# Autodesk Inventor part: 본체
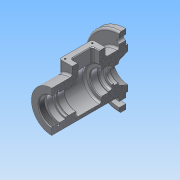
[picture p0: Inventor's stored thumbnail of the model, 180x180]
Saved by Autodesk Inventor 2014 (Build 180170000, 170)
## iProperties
Created: 2017-05
Part Number: 본체
Material: 알루미늄 6061
Document SubType Name: Modeling
Designer: SCD-A14
Density: 2.71 g/cm^3
Appearance: 알루미늄 - 평지
Mass: 682.14 g
Surface Area: 618.19 cm^2
Volume: 251.712 cm^3
Author: SCD-A14
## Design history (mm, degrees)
sketch "스케치1"
  geometry: C1 r 31 at (0, 0); 1 further point
  constraints: 1 centre point, 1 coincident
  dimensions: "d0" = 62 diameter of C1
extrude "돌출1" new body sketch "스케치1" distance "d1" = 115; taper "d2" = 0 deg
sketch "스케치2"
  geometry: 2 further points
  constraints: 1 coincident
hole "구멍1" sketch "스케치2" at (0, 0) diameter "d3" = 40.376; stored, may be unused: countersink angle "d7" = 90 deg, drill point angle "d9" = 0 deg; dims "d4" = 6, "d5" = 4, "d6" = 2, "d8" = 9
sketch "스케치3"
  geometry: C1 r 24 at (0, 0); 1 further point
  constraints: 1 centre point, 1 coincident
  dimensions: "d10" = 48 diameter of C1
extrude "돌출2" cut sketch "스케치3" distance "d11" = 3; taper "d12" = 0 deg
sketch "스케치4"
  geometry: C1 r 20 at (0, 0); 1 further point
  constraints: 1 centre point, 1 coincident
  dimensions: "d13" = 40 diameter of C1
extrude "돌출3" cut sketch "스케치4" distance "d14" = 9; taper "d15" = 0 deg
node "작업 평면1"
sketch "스케치5"
  geometry: C1 r 18.5 at (0, 0); 1 further point
  constraints: 1 centre point, 1 coincident
  dimensions: "d17" = 37 diameter of C1
extrude "돌출4" cut sketch "스케치5" distance "d18" = 1.75; taper "d19" = 0 deg
sketch "스케치6"
  geometry: C1 r 17.5 at (0, 0); 1 further point
  constraints: 1 centre point, 1 coincident
  dimensions: "d20" = 35 diameter of C1
extrude "돌출5" cut sketch "스케치6" distance "d21" = 65; taper "d22" = 0 deg
sketch "스케치7"
  geometry: L1 (-31, -115)-(31, -115) reference; L2 (-31, 0)-(31, 0) reference; L3 (0, -115)-(22, -115); L4 (-31, -115)-(31, -115) reference; L5 (0, -115)-(0, -101); L6 (0, -101)-(16, -101); L7 (16, -101)-(22, -115); 1 further point
  constraints: 8 end point, 2 perpendicular, 1 midpoint, 1 point on line
  dimensions: "d23" = 22 distance of L3.start L3.end; "d24" = 14 distance of L3.start L5.end; "d25" = 16 distance of L5.end L6.end
revolve "회전1" sketch "스케치7" stored, may be unused: angle "d26" = 90 deg
sketch "스케치8"
  geometry: C1 r 12.5 at (0, 0); 1 further point
  constraints: 1 centre point, 1 coincident
  dimensions: "d27" = 25 diameter of C1
extrude "돌출6" cut sketch "스케치8" distance "d28" = 7.3; taper "d29" = 0 deg
sketch "스케치9"
  geometry: C1 r 10 at (0, 0); 1 further point
  constraints: 1 centre point, 1 coincident
  dimensions: "d30" = 20 diameter of C1
extrude "돌출7" cut sketch "스케치9" distance "d31" = 2.7; taper "d32" = 0 deg
sketch "스케치10"
  geometry: C1 r 16.5 at (0, 0); 1 further point
  constraints: 1 centre point, 1 coincident
  dimensions: "d33" = 33 diameter of C1
extrude "돌출8" cut sketch "스케치10" distance "d34" = 5; taper "d35" = 0 deg
node "작업 평면2"
sketch "스케치11"
  geometry: C1 r 26 at (0, 0); 1 further point
  constraints: 1 centre point, 1 coincident
  dimensions: "d37" = 52 diameter of C1
extrude "돌출9" cut sketch "스케치11" distance "d38" = 38; taper "d39" = 0 deg
node "작업 평면3"
sketch "스케치12"
  geometry: C1 r 53 at (0, 0); 1 further point
  constraints: 1 centre point, 1 coincident
  dimensions: "d41" = 106 diameter of C1
extrude "돌출10" join sketch "스케치12" distance "d42" = 13; taper "d43" = 0 deg
sketch "스케치15"
  geometry: A1 r 45.5 centre (0, 0) between (45.5, 0) and (0, 45.5); A2 r 4 centre (0, 41.5) between (0, 45.5) and (0, 37.5); A3 r 37.5 centre (0, 0) between (37.5, 0) and (0, 37.5); A4 r 4 centre (41.5, 0) between (37.5, 0) and (45.5, 0); 1 further point
  constraints: 8 point on circle, 4 centre point, 1 coincident, 1 horizontal alignment, 1 vertical alignment
  dimensions: "d109" = 37.5 radius of A3; "d110" = 45.5 radius of A1; "d111" = 4 radius of A2; "d112" = 4 radius of A4; "d113" = 41.5 distance of point (0, 0) A4.centre; "d114" = 41.5 distance of A2.centre point (0, 0)
extrude "돌출11" cut sketch "스케치15" stored distance "d57" = 13; taper "d58" = 0 deg
node "작업 평면4"
sketch "스케치16"
  geometry: L1 (20, -31)-(-20, -31); L2 (-20, -31)-(-20, -81); L3 (-20, -81)-(20, -81); L4 (20, -81)-(20, -31); L5 (20, -31)-(-20, -81); L6 (-20, -31)-(20, -81); 2 further points
  constraints: 12 end point, 2 midpoint, 2 parallel, 1 horizontal, 1 perpendicular
  dimensions: "d64" = 56 distance of point (0, 0) point (0, -56); "d65" = 50 distance between parallel lines of L3 L1; "d66" = 40 distance between parallel lines of L4 L2; "d67" = 0 horizontal distance of point (0, 0) point (0, -56)
extrude "돌출12" join sketch "스케치16" stored distance "d68" = 10; taper "d69" = 0 deg
sketch "스케치17"
  geometry: L1 (-31, 99)-(31, 99) reference; L2 (31, 0)-(-31, 0) reference; L3 (20, 81)-(20, 31) reference; L4 (20, 31)-(-20, 31) reference; L5 (-20, 31)-(-20, 81) reference; L6 (-20, 81)-(20, 81) reference; L7 (-11, 40)-(11, 40); L8 (11, 40)-(11, 72); L9 (11, 72)-(-11, 72); L10 (-11, 72)-(-11, 40); 5 further points
  constraints: 8 end point, 4 midpoint, 2 parallel, 1 horizontal, 1 horizontal alignment, 1 perpendicular, 1 vertical alignment
  dimensions: "d70" = 22 distance between parallel lines of L10 L8; "d71" = 32 distance between parallel lines of L9 L7
extrude "돌출13" cut sketch "스케치17" distance "d72" = 38.75; taper "d73" = 0 deg
sketch "스케치18"
  geometry: L1 (-31, 99)-(31, 99) reference; L2 (31, 0)-(-31, 0) reference; L3 (20, 81)-(20, 31) reference; L4 (20, 31)-(-20, 31) reference; L5 (-20, 31)-(-20, 81) reference; L6 (-20, 81)-(20, 81) reference; L7 (-15.5, 35.5)-(15.5, 35.5); L8 (15.5, 35.5)-(15.5, 76.5); L9 (15.5, 76.5)-(-15.5, 76.5); L10 (-15.5, 76.5)-(-15.5, 35.5); 9 further points
  constraints: 8 end point, 4 coincident, 4 midpoint, 2 parallel, 1 horizontal, 1 horizontal alignment, 1 perpendicular, 1 vertical alignment
  dimensions: "d74" = 41 distance of L9.end L7.start; "d75" = 31 distance of L7.start L7.end
hole "구멍2" sketch "스케치18" at (-15.5, 35.5), (-15.5, 76.5), (15.5, 76.5), (15.5, 35.5) diameter "d76" = 2.459; stored, may be unused: countersink angle "d80" = 90 deg, drill point angle "d82" = 118 deg; dims "d77" = 6, "d78" = 4, "d79" = 2, "d81" = 8
sketch "스케치19"
  geometry: L1 (68, -13)-(68, -75) reference; L2 (-31, -75)-(-31, -13) reference; L3 (50, -20.315)-(0, -20.315) reference; L4 (0, -20.315)-(0, -20.315) reference; L5 (0, -20.315)-(50, -20.315) reference; L6 (50, -20.315)-(50, -20.315) reference; L7 (0, -20.315)-(50, -20.315) reference; L8 (0, 0)-(0, -20.315) reference; L9 (50, 0)-(0, 0) reference; L10 (50, 0)-(50, -20.315) reference; 2 further points
  constraints: 1 other
  dimensions: "d83" = 56 distance from line of point (25, -8) L2; "d84" = 8 distance from line of L9 point (25, -8)
extrude "돌출14" join sketch "스케치19" distance "d85" = 0.5; taper "d86" = 0 deg
revolve "회전2" stored, may be unused: angle "d88" = 90 deg
fillet "모깎기1" dims "d89" = 3
chamfer "모따기1" distance "d90" = 1; stored, may be unused: second distance "d91" = 2, angle "d92" = 30 deg
fillet "모깎기2" dims "d93" = 3
chamfer "모따기2" distance "d94" = 1; stored, may be unused: second distance "d95" = 2, angle "d96" = 30 deg
fillet "모깎기3" dims "d97" = 3
chamfer "모따기3" distance "d98" = 1; stored, may be unused: second distance "d99" = 2, angle "d100" = 30 deg
fillet "모깎기4" dims "d101" = 0.3
fillet "모깎기5" dims "d102" = 3
fillet "모깎기6" dims "d103" = 3
fillet "모깎기7" dims "d104" = 3
chamfer "모따기4" distance "d105" = 1; stored, may be unused: second distance "d106" = 2, angle "d107" = 30 deg
fillet "모깎기8" dims "d108" = 3
sketch "스케치21"
  geometry: C1 r 53 at (0, 0); C2 r 31 at (0, 0); 1 further point
  constraints: 2 centre point, 2 coincident
  dimensions: "d115" = 106 diameter of C1; "d116" = 62 diameter of C2
extrude "돌출15" cut sketch "스케치21" distance "d117" = 3; taper "d118" = 0 deg
fillet "모깎기9" dims "d119" = 3
fillet "모깎기10" dims "d120" = 3
sketch "스케치22"
  geometry: L1 (22, -115)-(-22, -115) reference; L2 (0, -115)-(0, -101); L3 (0, -102)-(0, -112) reference; L4 (0, -101)-(16, -101); L5 (0, -115)-(22, -115); L6 (16, -101)-(22, -115); 1 further point
  constraints: 8 end point, 1 collinear, 1 midpoint, 1 perpendicular, 1 point on line
  dimensions: "d123" = 14 distance of L2.start L2.end; "d124" = 16 distance of L2.end L4.end; "d125" = 22 distance of L2.start L5.end
revolve "회전3" sketch "스케치22" stored, may be unused: angle "d126" = 90 deg
sketch "스케치23"
  geometry: C1 r 12.5 at (0, 0); 1 further point
  constraints: 1 centre point, 1 coincident
  dimensions: "d127" = 25 diameter of C1
extrude "돌출16" cut sketch "스케치23" stored distance "d128" = 3; taper "d129" = 0 deg
fillet "모깎기11" dims "d130" = 3
chamfer "모따기5" distance "d131" = 0.7; stored, may be unused: second distance "d132" = 2, angle "d133" = 30 deg
fillet "모깎기12" dims "d134" = 0.3
node "솔리드1"
pattern_circular "원형 패턴1" dims angle "d60" = 360 deg
node "투영된 루프1"
node "투영된 루프2"
node "투영된 루프3"
node "투영된 루프4"
node "투영된 루프5"
sketch "스케치20"
  geometry: L1 (22, -115)-(-22, -115) reference; L2 (31, -99)-(-31, -99) reference; L3 (-31, 0)-(31, 0) reference; L4 (23.685, -81)-(23.685, -31) reference; L5 (23.685, -31)-(23.685, -31) reference; L6 (23.685, -31)-(23.685, -81) reference; L7 (23.685, -81)-(23.685, -81) reference; L8 (31, -99)-(-31, -99) reference; L9 (16, -101)-(22, -115); L10 (0, -115)-(22, -115); L11 (0, -115)-(0, -101); L12 (0, -101)-(16, -101); 3 further points
  constraints: 8 end point, 2 midpoint, 2 perpendicular, 1 collinear, 1 point on line
  dimensions: "d121" = 14 distance of L10.start L11.end; "d122" = 16 distance of L11.end L9.start
node "투영된 루프6"
other parameters: "d16" = -26, "d36" = -37, "d40" = -16, "d62" = 44
